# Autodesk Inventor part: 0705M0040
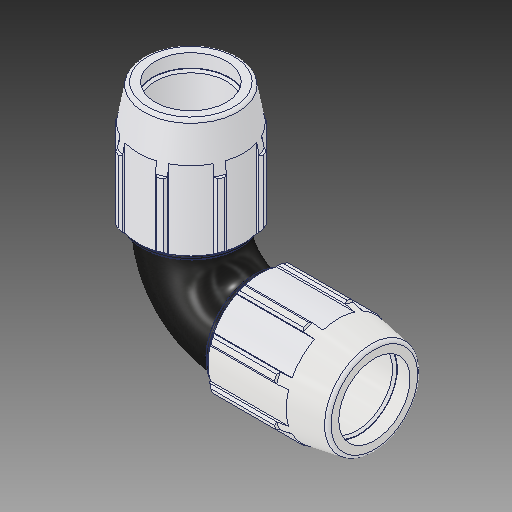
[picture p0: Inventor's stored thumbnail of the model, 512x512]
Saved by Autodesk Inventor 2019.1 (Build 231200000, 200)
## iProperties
Created: 2017-02
Part Number: 0705M0040
Material: PVC-Piping
Description: PLASSON 90° ELBOW 4'' - 4''
Document SubType Name: Modeling
Designer: KIM
Mass: 92.6774 g
Surface Area: 199.44 cm^2
Volume: 66.1981 cm^3
Density: 1.4 g/cm^3
Appearance: PTFE
Author: KIM
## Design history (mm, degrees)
derived "0705M0.ipt"
feature "Solid1::0705M0.ipt"
tag "TaggingFeature1"
body "Solid1"
other parameters: "d2" = 114.1, "d4" = 24.48983, "d5" = 73.4695, "d7" = 181.102, "d9" = 41.98257, "d11" = 7.34695, "d13" = 120 deg, "d14" = 148.33, "d15" = 10 deg, "d16" = 157.55874, "d18" = 5.705, "d19" = 35 deg, "d20" = 17.5 deg, "d21" = 168.42486, "d23" = 0, "d25" = 360 deg, "d27" = 3.62204, "d33" = 2.282, "d42" = 108.73486, "d43" = 5.43306, "d46" = 3.423, "d51" = 293.878, "d59" = 90 deg, "d63" = 196.088, "d64" = 102.69, "d67" = 135.8265, "d68" = 3.67348, "d70" = 90 deg, "d_" = 114.1, "E_" = 181.102, "A_" = 293.878, "l_" = 196.088
